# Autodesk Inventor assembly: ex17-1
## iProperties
Shininess: 64.0
Length Units: 11269
Angle Units: 11279
Time Units: 11290
Mass Units: 11283
Length Display Precision: 3
Angle Display Precision: 2
Compacted: True
Created: 2002-11
Part Number: ex17-1
Document SubType Name: Assembly
Designer: E. MOSS
Density: 0.0
Volumn: 0.0
Area: 0.0
PropertySet Name: Model Information
Control State: 0
Master: False
Checked Out: False
Author: E. MOSS
